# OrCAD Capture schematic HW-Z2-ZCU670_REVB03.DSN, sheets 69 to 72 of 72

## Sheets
69 069 Zynq Per-pin Decoupling 1: size Custom
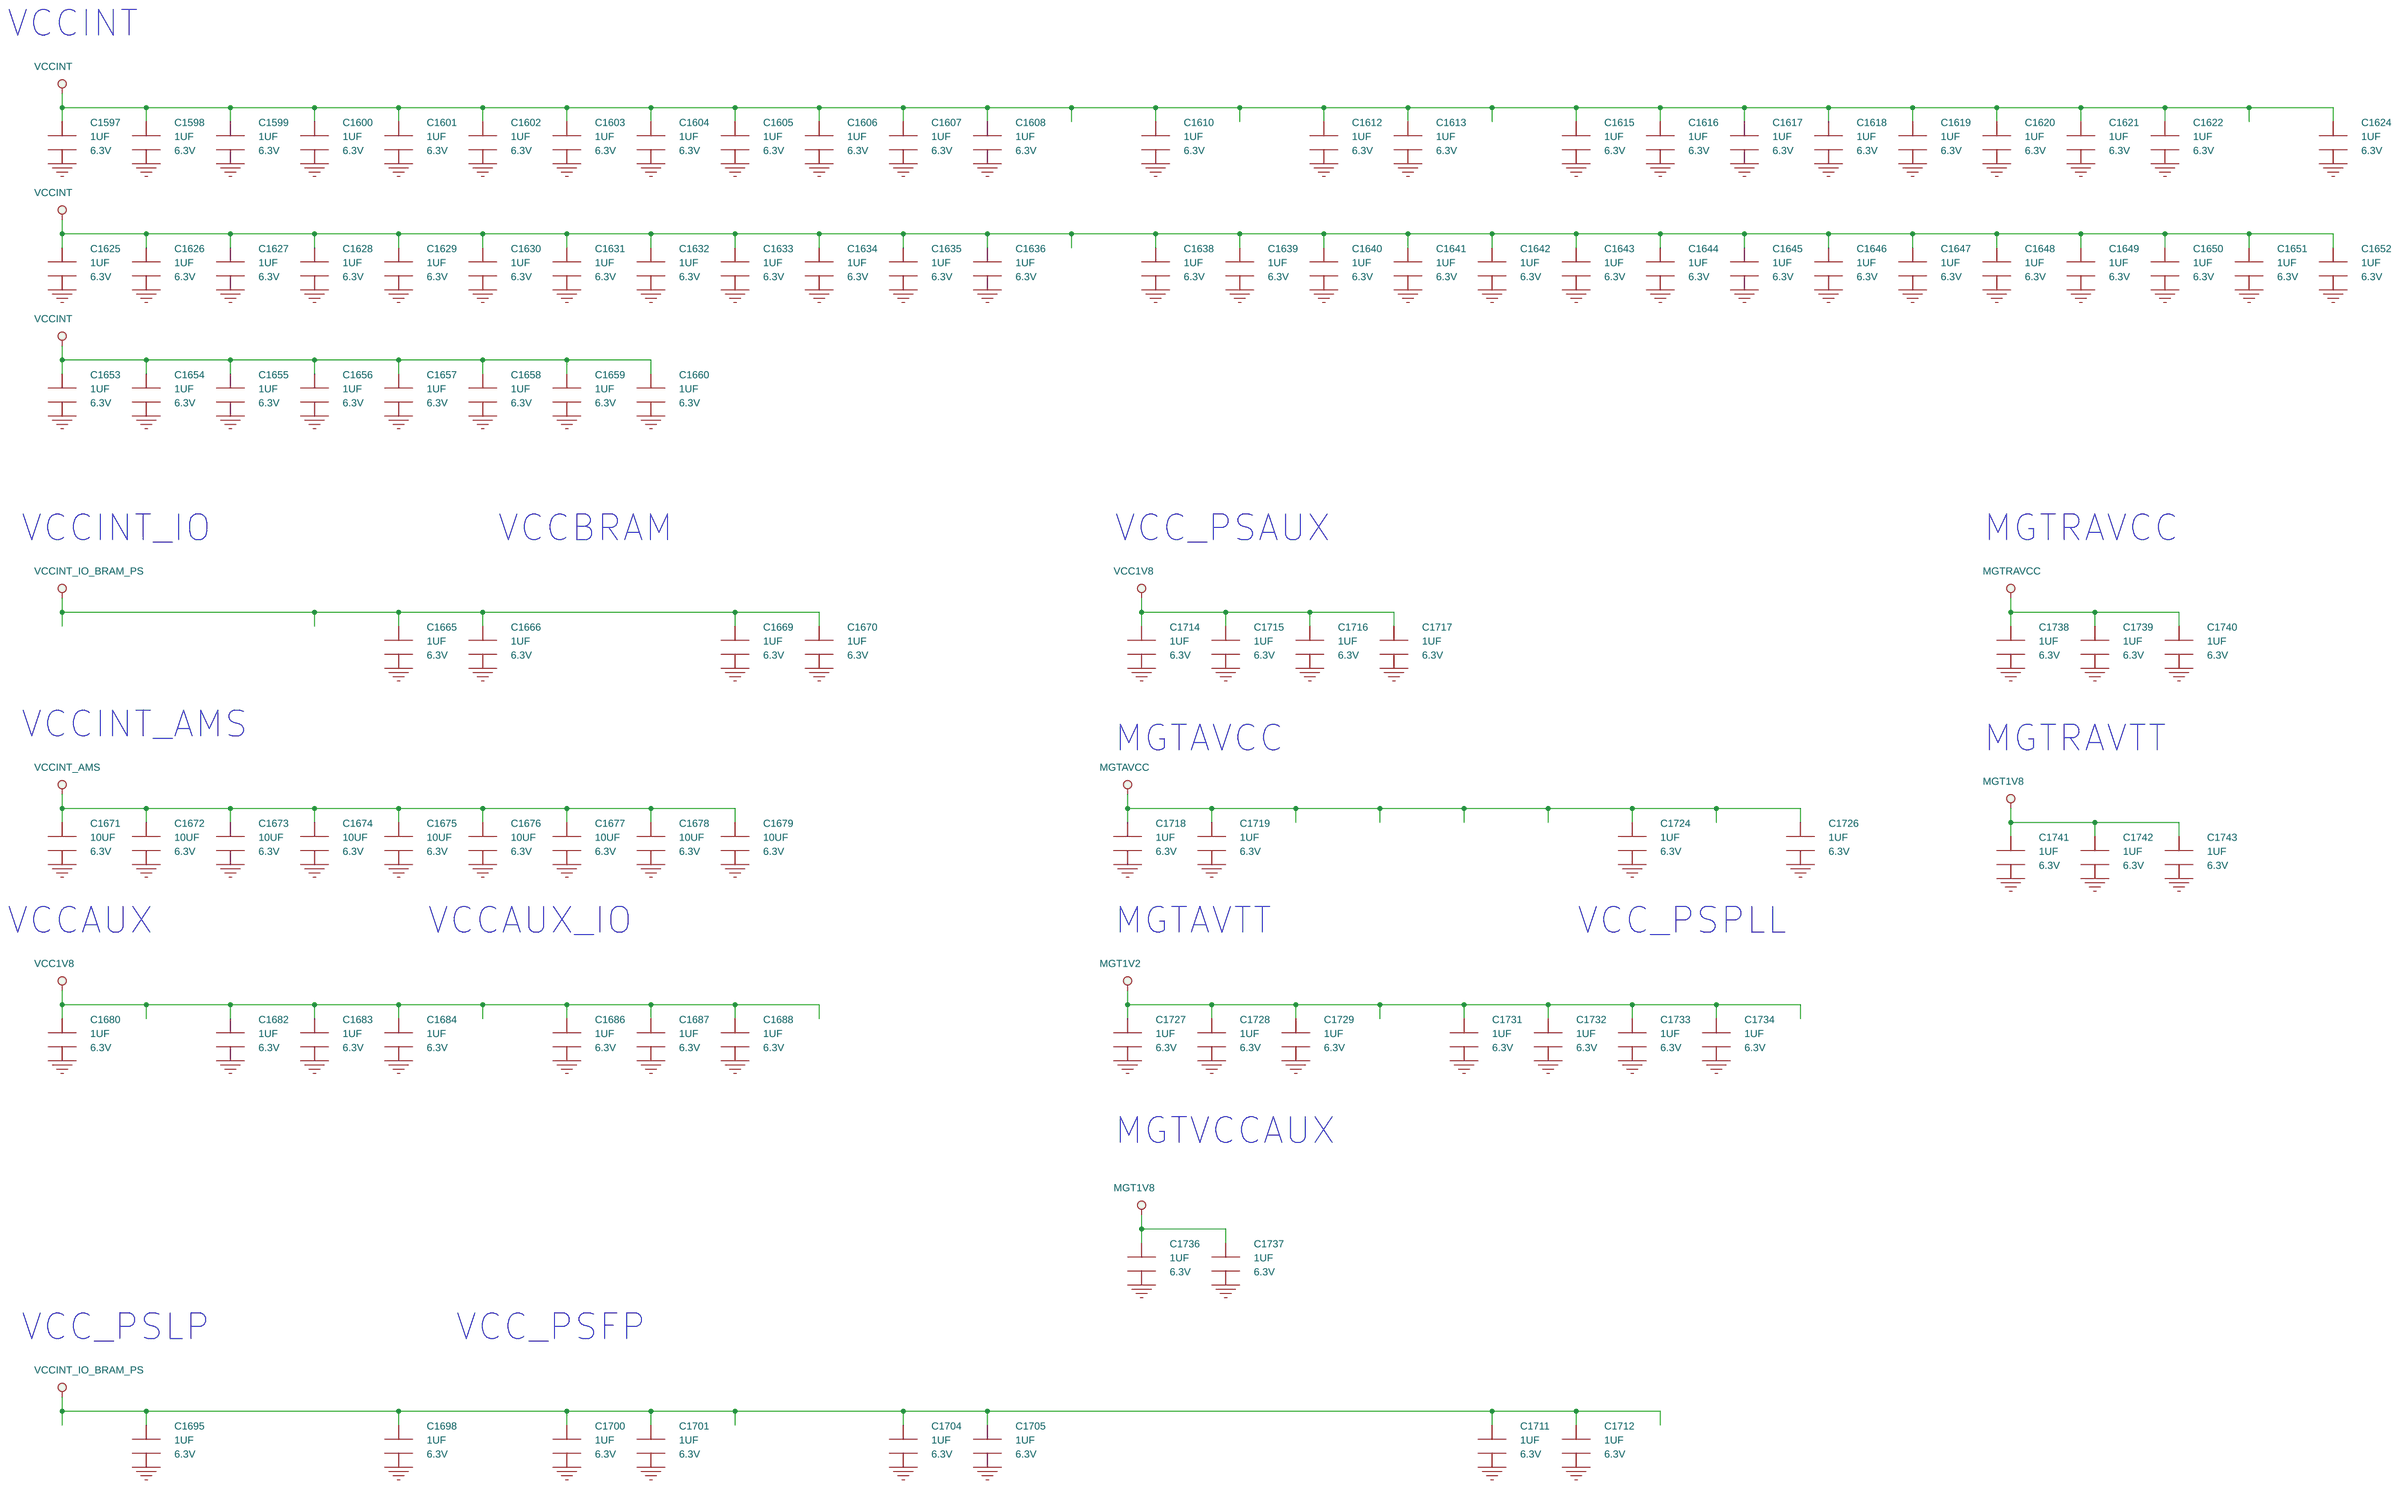
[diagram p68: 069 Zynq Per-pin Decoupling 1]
70 070 Zynq Per-pin Decoupling 2: size Custom
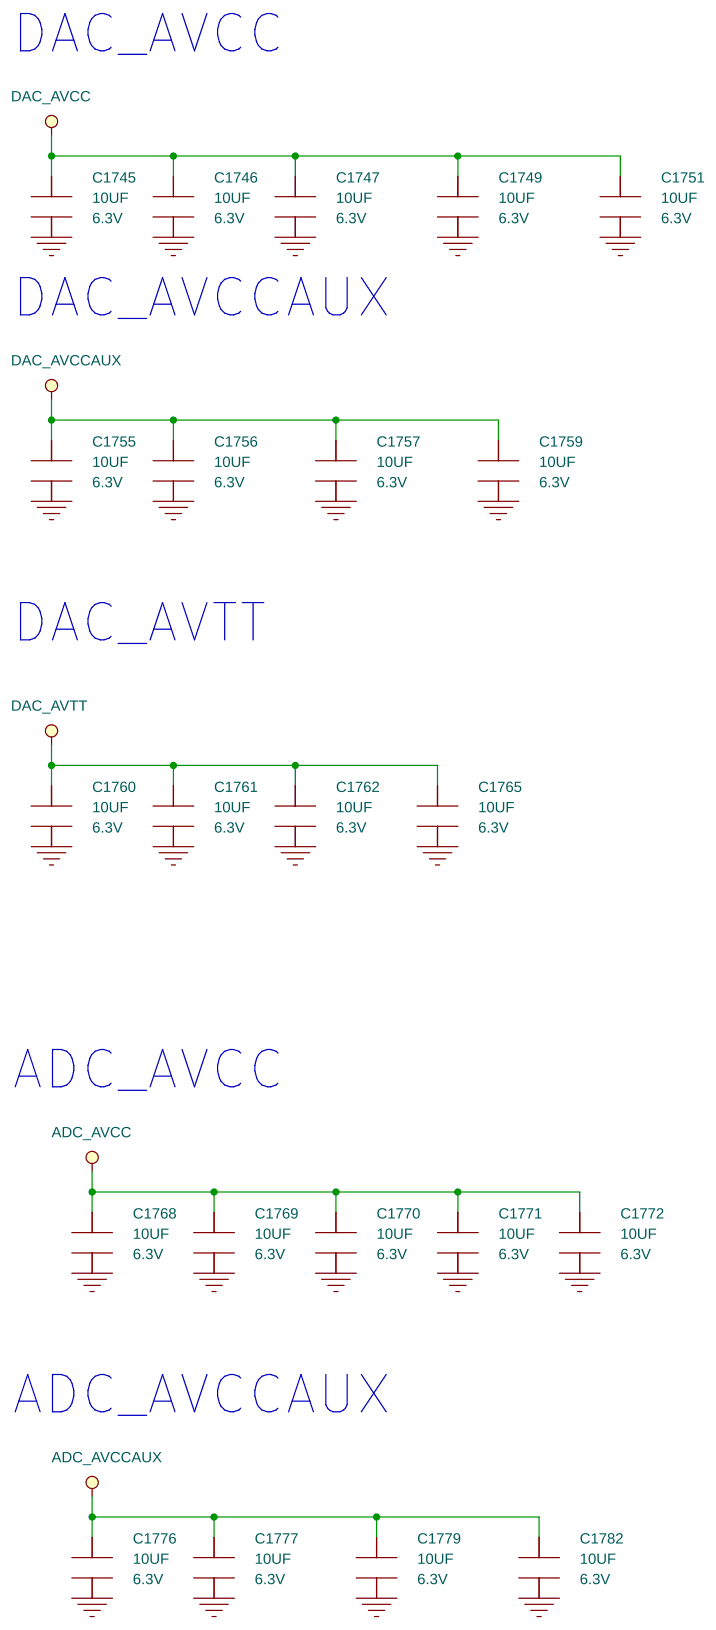
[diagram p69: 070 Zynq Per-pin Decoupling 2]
71 071 1588 eCPRI Power 1: size Custom
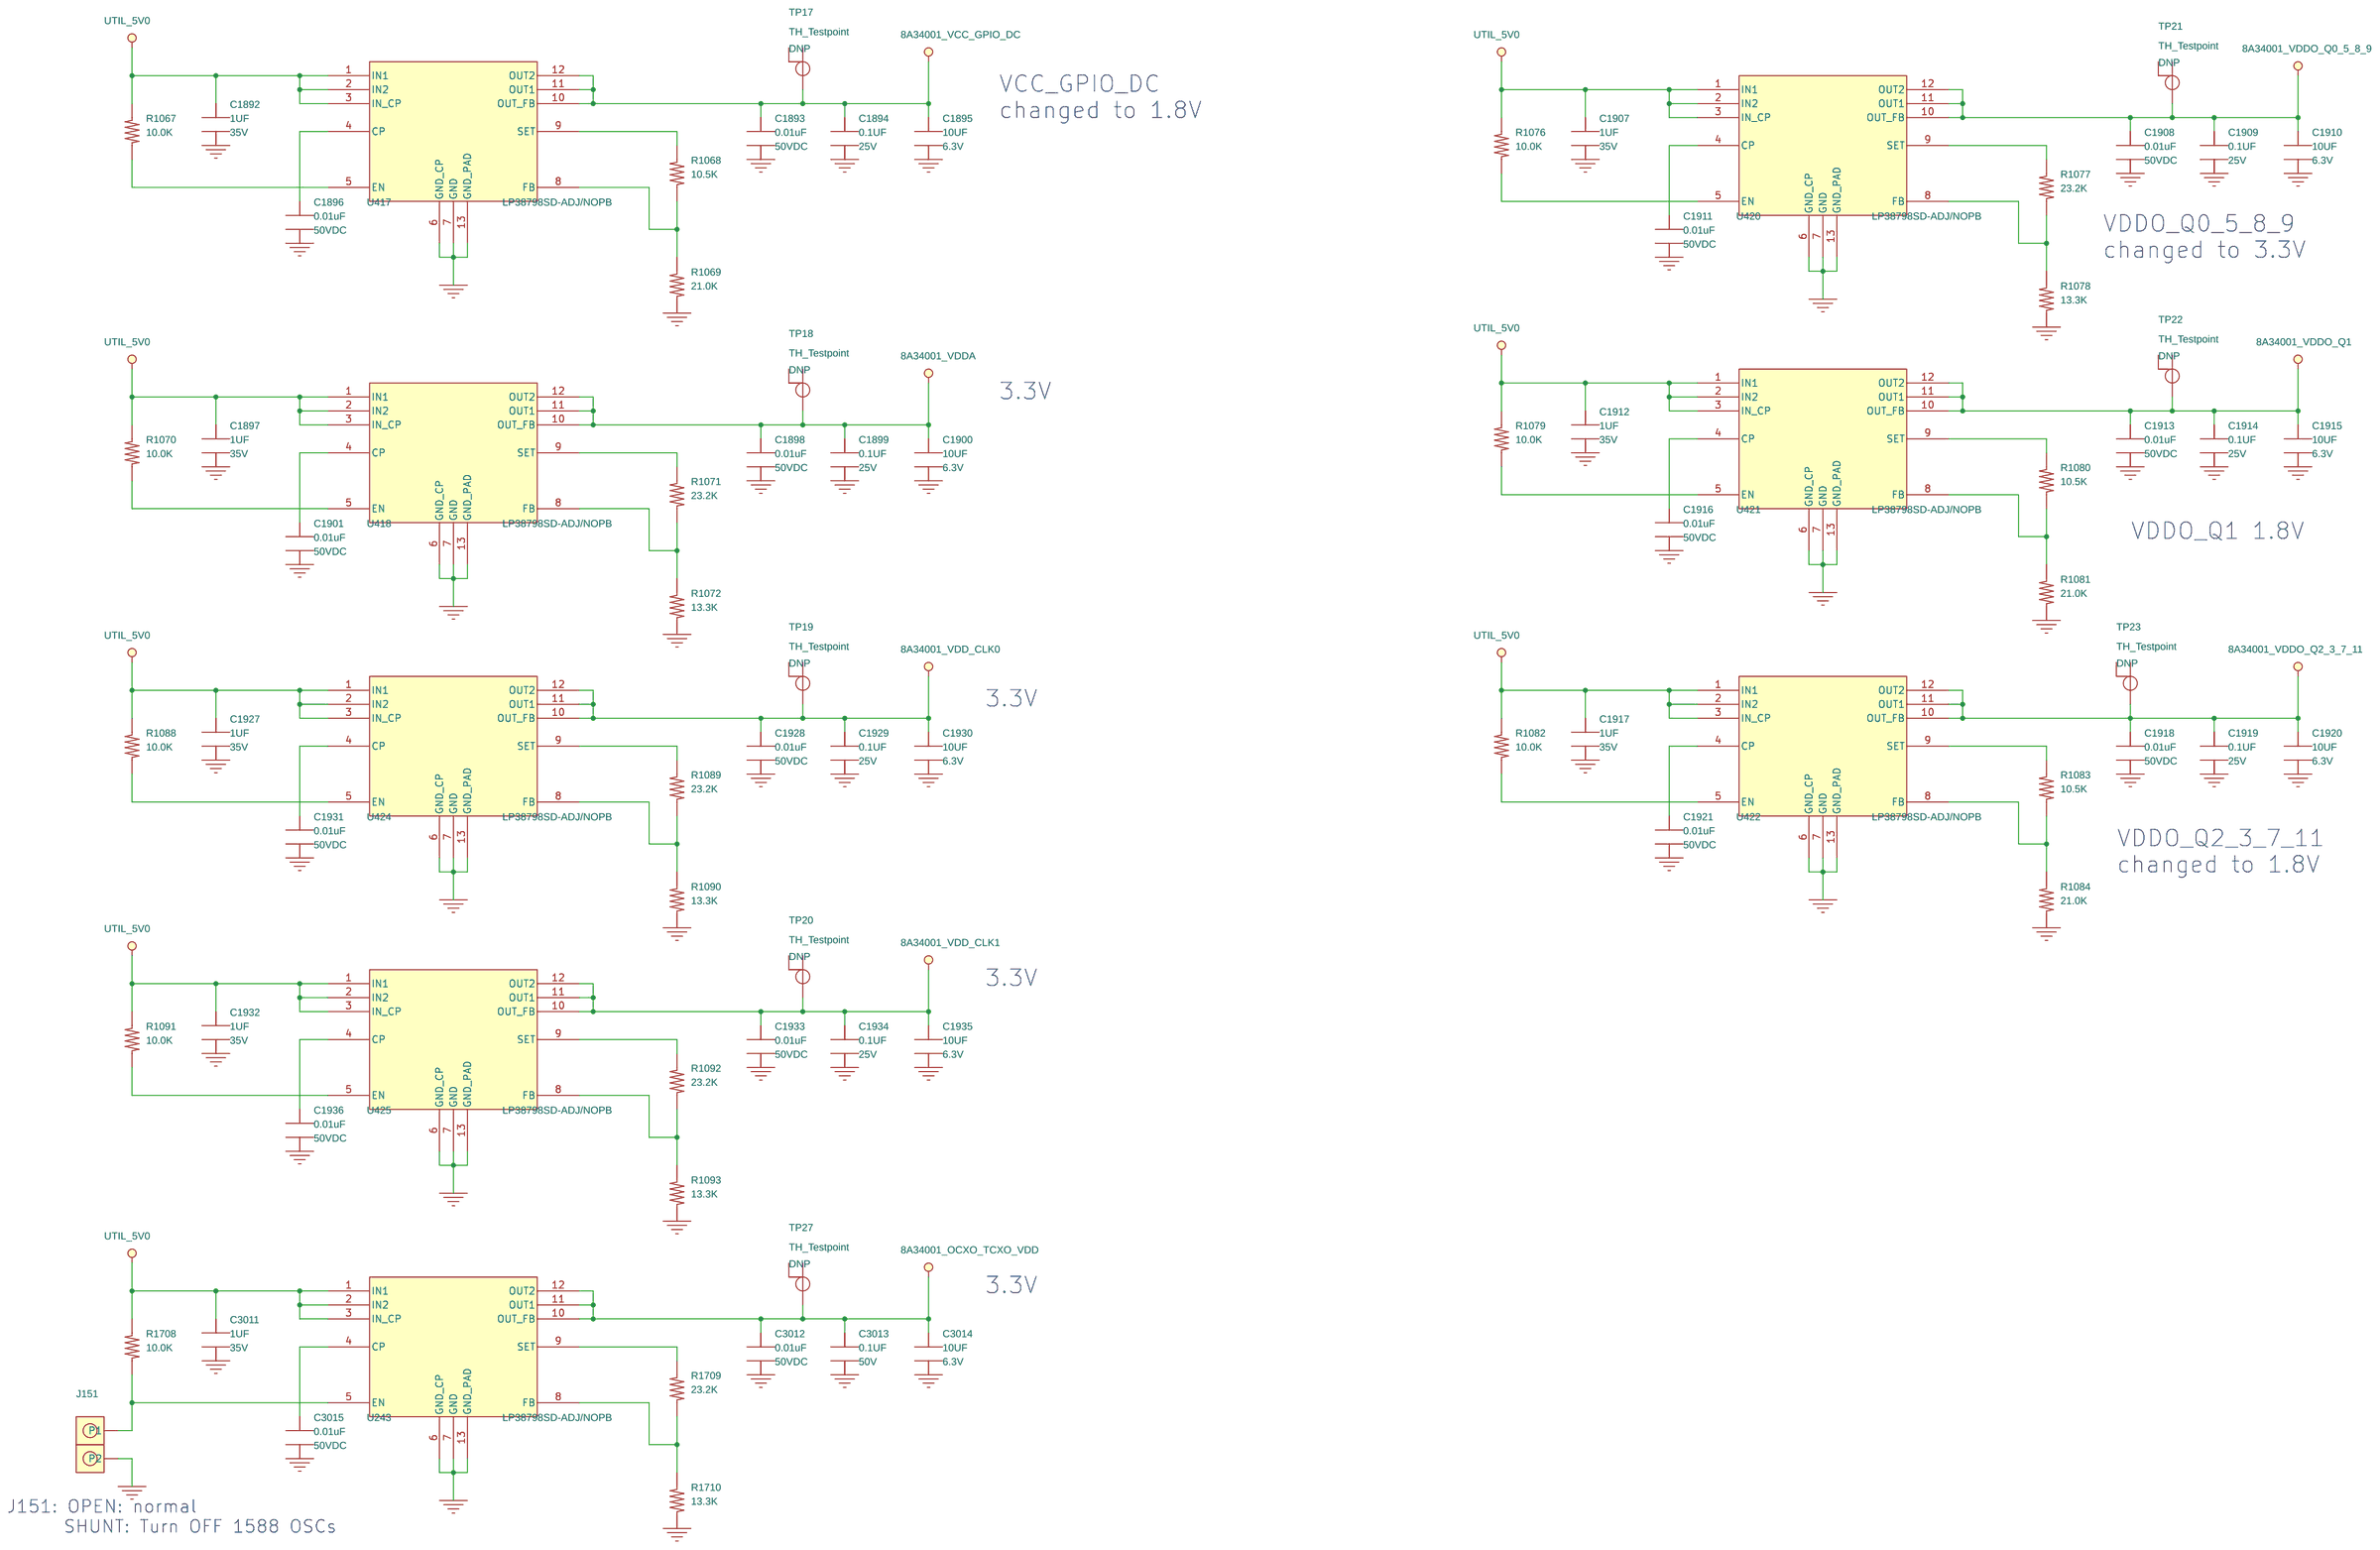
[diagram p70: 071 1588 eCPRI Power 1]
72 072 1588 eCPRI Power 2: size Custom
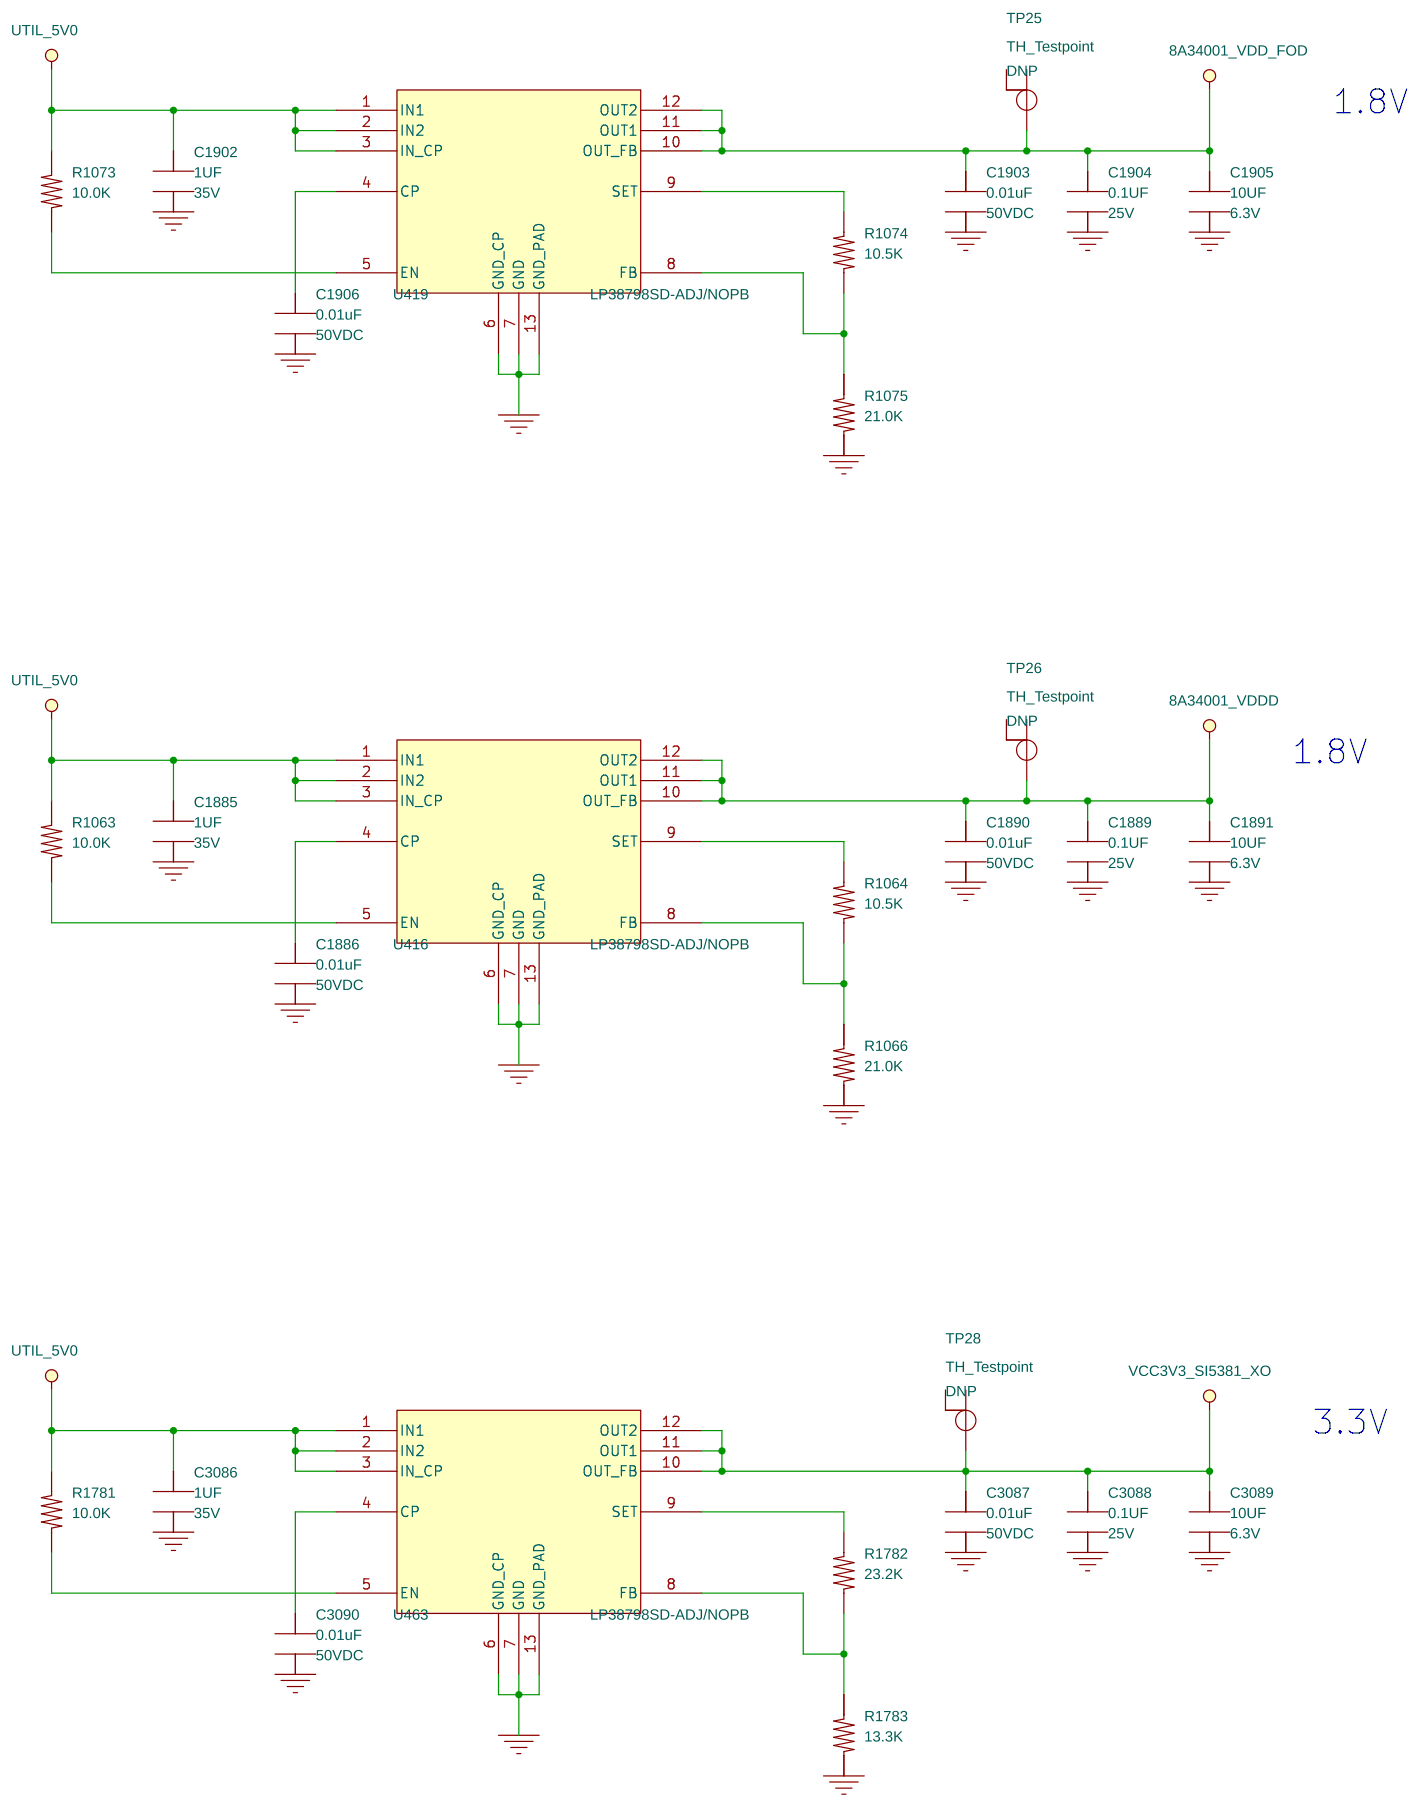
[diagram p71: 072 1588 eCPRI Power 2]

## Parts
sheet 069 Zynq Per-pin Decoupling 1
C1597  1UF  [CAPC60X30X40]
C1598  1UF  [CAPC60X30X40]
C1599  1UF  [CAPC60X30X40]
C1600  1UF  [CAPC60X30X40]
C1601  1UF  [CAPC60X30X40]
C1602  1UF  [CAPC60X30X40]
C1603  1UF  [CAPC60X30X40]
C1604  1UF  [CAPC60X30X40]
C1605  1UF  [CAPC60X30X40]
C1606  1UF  [CAPC60X30X40]
C1607  1UF  [CAPC60X30X40]
C1608  1UF  [CAPC60X30X40]
C1610  1UF  [CAPC60X30X40]
C1612  1UF  [CAPC60X30X40]
C1613  1UF  [CAPC60X30X40]
C1615  1UF  [CAPC60X30X40]
C1616  1UF  [CAPC60X30X40]
C1617  1UF  [CAPC60X30X40]
C1618  1UF  [CAPC60X30X40]
C1619  1UF  [CAPC60X30X40]
C1620  1UF  [CAPC60X30X40]
C1621  1UF  [CAPC60X30X40]
C1622  1UF  [CAPC60X30X40]
C1624  1UF  [CAPC60X30X40]
C1625  1UF  [CAPC60X30X40]
C1626  1UF  [CAPC60X30X40]
C1627  1UF  [CAPC60X30X40]
C1628  1UF  [CAPC60X30X40]
C1629  1UF  [CAPC60X30X40]
C1630  1UF  [CAPC60X30X40]
C1631  1UF  [CAPC60X30X40]
C1632  1UF  [CAPC60X30X40]
C1633  1UF  [CAPC60X30X40]
C1634  1UF  [CAPC60X30X40]
C1635  1UF  [CAPC60X30X40]
C1636  1UF  [CAPC60X30X40]
C1638  1UF  [CAPC60X30X40]
C1639  1UF  [CAPC60X30X40]
C1640  1UF  [CAPC60X30X40]
C1641  1UF  [CAPC60X30X40]
C1642  1UF  [CAPC60X30X40]
C1643  1UF  [CAPC60X30X40]
C1644  1UF  [CAPC60X30X40]
C1645  1UF  [CAPC60X30X40]
C1646  1UF  [CAPC60X30X40]
C1647  1UF  [CAPC60X30X40]
C1648  1UF  [CAPC60X30X40]
C1649  1UF  [CAPC60X30X40]
C1650  1UF  [CAPC60X30X40]
C1651  1UF  [CAPC60X30X40]
C1652  1UF  [CAPC60X30X40]
C1653  1UF  [CAPC60X30X40]
C1654  1UF  [CAPC60X30X40]
C1655  1UF  [CAPC60X30X40]
C1656  1UF  [CAPC60X30X40]
C1657  1UF  [CAPC60X30X40]
C1658  1UF  [CAPC60X30X40]
C1659  1UF  [CAPC60X30X40]
C1660  1UF  [CAPC60X30X40]
C1665  1UF  [CAPC60X30X40]
C1666  1UF  [CAPC60X30X40]
C1669  1UF  [CAPC60X30X40]
C1670  1UF  [CAPC60X30X40]
C1671  10UF  [CAPC100X50X70]
C1672  10UF  [CAPC100X50X70]
C1673  10UF  [CAPC100X50X70]
C1674  10UF  [CAPC100X50X70]
C1675  10UF  [CAPC100X50X70]
C1676  10UF  [CAPC100X50X70]
C1677  10UF  [CAPC100X50X70]
C1678  10UF  [CAPC100X50X70]
C1679  10UF  [CAPC100X50X70]
C1680  1UF  [CAPC60X30X40]
C1682  1UF  [CAPC60X30X40]
C1683  1UF  [CAPC60X30X40]
C1684  1UF  [CAPC60X30X40]
C1686  1UF  [CAPC60X30X40]
C1687  1UF  [CAPC60X30X40]
C1688  1UF  [CAPC60X30X40]
C1695  1UF  [CAPC60X30X40]
C1698  1UF  [CAPC60X30X40]
C1700  1UF  [CAPC60X30X40]
C1701  1UF  [CAPC60X30X40]
C1704  1UF  [CAPC60X30X40]
C1705  1UF  [CAPC60X30X40]
C1711  1UF  [CAPC60X30X40]
C1712  1UF  [CAPC60X30X40]
C1714  1UF  [CAPC60X30X40]
C1715  1UF  [CAPC60X30X40]
C1716  1UF  [CAPC60X30X40]
C1717  1UF  [CAPC60X30X40]
C1718  1UF  [CAPC60X30X40]
C1719  1UF  [CAPC60X30X40]
C1724  1UF  [CAPC60X30X40]
C1726  1UF  [CAPC60X30X40]
C1727  1UF  [CAPC60X30X40]
C1728  1UF  [CAPC60X30X40]
C1729  1UF  [CAPC60X30X40]
C1731  1UF  [CAPC60X30X40]
C1732  1UF  [CAPC60X30X40]
C1733  1UF  [CAPC60X30X40]
C1734  1UF  [CAPC60X30X40]
C1736  1UF  [CAPC60X30X40]
C1737  1UF  [CAPC60X30X40]
C1738  1UF  [CAPC60X30X40]
C1739  1UF  [CAPC60X30X40]
C1740  1UF  [CAPC60X30X40]
C1741  1UF  [CAPC60X30X40]
C1742  1UF  [CAPC60X30X40]
C1743  1UF  [CAPC60X30X40]
sheet 070 Zynq Per-pin Decoupling 2
C1745  10UF  [CAPC100X50X70]
C1746  10UF  [CAPC100X50X70]
C1747  10UF  [CAPC100X50X70]
C1749  10UF  [CAPC100X50X70]
C1751  10UF  [CAPC100X50X70]
C1755  10UF  [CAPC100X50X70]
C1756  10UF  [CAPC100X50X70]
C1757  10UF  [CAPC100X50X70]
C1759  10UF  [CAPC100X50X70]
C1760  10UF  [CAPC100X50X70]
C1761  10UF  [CAPC100X50X70]
C1762  10UF  [CAPC100X50X70]
C1765  10UF  [CAPC100X50X70]
C1768  10UF  [CAPC100X50X70]
C1769  10UF  [CAPC100X50X70]
C1770  10UF  [CAPC100X50X70]
C1771  10UF  [CAPC100X50X70]
C1772  10UF  [CAPC100X50X70]
C1776  10UF  [CAPC100X50X70]
C1777  10UF  [CAPC100X50X70]
C1779  10UF  [CAPC100X50X70]
C1782  10UF  [CAPC100X50X70]
sheet 071 1588 eCPRI Power 1
C1892  1UF  [CAPC100X50X60]
C1893  0.01uF  [CAPC100X50X55]
C1894  0.1UF  [CAPC100X50X55]
C1895  10UF  [CAPC100X50X70]
C1896  0.01uF  [CAPC100X50X55]
C1897  1UF  [CAPC100X50X60]
C1898  0.01uF  [CAPC100X50X55]
C1899  0.1UF  [CAPC100X50X55]
C1900  10UF  [CAPC100X50X70]
C1901  0.01uF  [CAPC100X50X55]
C1907  1UF  [CAPC100X50X60]
C1908  0.01uF  [CAPC100X50X55]
C1909  0.1UF  [CAPC100X50X55]
C1910  10UF  [CAPC100X50X70]
C1911  0.01uF  [CAPC100X50X55]
C1912  1UF  [CAPC100X50X60]
C1913  0.01uF  [CAPC100X50X55]
C1914  0.1UF  [CAPC100X50X55]
C1915  10UF  [CAPC100X50X70]
C1916  0.01uF  [CAPC100X50X55]
C1917  1UF  [CAPC100X50X60]
C1918  0.01uF  [CAPC100X50X55]
C1919  0.1UF  [CAPC100X50X55]
C1920  10UF  [CAPC100X50X70]
C1921  0.01uF  [CAPC100X50X55]
C1927  1UF  [CAPC100X50X60]
C1928  0.01uF  [CAPC100X50X55]
C1929  0.1UF  [CAPC100X50X55]
C1930  10UF  [CAPC100X50X70]
C1931  0.01uF  [CAPC100X50X55]
C1932  1UF  [CAPC100X50X60]
C1933  0.01uF  [CAPC100X50X55]
C1934  0.1UF  [CAPC100X50X55]
C1935  10UF  [CAPC100X50X70]
C1936  0.01uF  [CAPC100X50X55]
C3011  1UF  [CAPC100X50X60]
C3012  0.01uF  [CAPC100X50X55]
C3013  0.1UF  [CAPC100X50X55]
C3014  10UF  [CAPC100X50X70]
C3015  0.01uF  [CAPC100X50X55]
J151  HDR_1X2  [HDR_1X2]
R1067  10.0K  [RESC100X50X40]
R1068  10.5K  [RESC100X50X40]
R1069  21.0K  [RESC100X50X40]
R1070  10.0K  [RESC100X50X40]
R1071  23.2K  [RESC100X50X40]
R1072  13.3K  [RESC100X50X40]
R1076  10.0K  [RESC100X50X40]
R1077  23.2K  [RESC100X50X40]
R1078  13.3K  [RESC100X50X40]
R1079  10.0K  [RESC100X50X40]
R1080  10.5K  [RESC100X50X40]
R1081  21.0K  [RESC100X50X40]
R1082  10.0K  [RESC100X50X40]
R1083  10.5K  [RESC100X50X40]
R1084  21.0K  [RESC100X50X40]
R1088  10.0K  [RESC100X50X40]
R1089  23.2K  [RESC100X50X40]
R1090  13.3K  [RESC100X50X40]
R1091  10.0K  [RESC100X50X40]
R1092  23.2K  [RESC100X50X40]
R1093  13.3K  [RESC100X50X40]
R1708  10.0K  [RESC100X50X40]
R1709  23.2K  [RESC100X50X40]
R1710  13.3K  [RESC100X50X40]
TP17  TH_Testpoint  [TH_PAD]
TP18  TH_Testpoint  [TH_PAD]
TP19  TH_Testpoint  [TH_PAD]
TP20  TH_Testpoint  [TH_PAD]
TP21  TH_Testpoint  [TH_PAD]
TP22  TH_Testpoint  [TH_PAD]
TP23  TH_Testpoint  [TH_PAD]
TP27  TH_Testpoint  [TH_PAD]
U243  LP38798SD-ADJ/NOPB  [WSON05PX400X400X100_12_260X300]
U417  LP38798SD-ADJ/NOPB  [WSON05PX400X400X100_12_260X300]
U418  LP38798SD-ADJ/NOPB  [WSON05PX400X400X100_12_260X300]
U420  LP38798SD-ADJ/NOPB  [WSON05PX400X400X100_12_260X300]
U421  LP38798SD-ADJ/NOPB  [WSON05PX400X400X100_12_260X300]
U422  LP38798SD-ADJ/NOPB  [WSON05PX400X400X100_12_260X300]
U424  LP38798SD-ADJ/NOPB  [WSON05PX400X400X100_12_260X300]
U425  LP38798SD-ADJ/NOPB  [WSON05PX400X400X100_12_260X300]
sheet 072 1588 eCPRI Power 2
C1885  1UF  [CAPC100X50X60]
C1886  0.01uF  [CAPC100X50X55]
C1889  0.1UF  [CAPC100X50X55]
C1890  0.01uF  [CAPC100X50X55]
C1891  10UF  [CAPC100X50X70]
C1902  1UF  [CAPC100X50X60]
C1903  0.01uF  [CAPC100X50X55]
C1904  0.1UF  [CAPC100X50X55]
C1905  10UF  [CAPC100X50X70]
C1906  0.01uF  [CAPC100X50X55]
C3086  1UF  [CAPC100X50X60]
C3087  0.01uF  [CAPC100X50X55]
C3088  0.1UF  [CAPC100X50X55]
C3089  10UF  [CAPC100X50X70]
C3090  0.01uF  [CAPC100X50X55]
R1063  10.0K  [RESC100X50X40]
R1064  10.5K  [RESC100X50X40]
R1066  21.0K  [RESC100X50X40]
R1073  10.0K  [RESC100X50X40]
R1074  10.5K  [RESC100X50X40]
R1075  21.0K  [RESC100X50X40]
R1781  10.0K  [RESC100X50X40]
R1782  23.2K  [RESC100X50X40]
R1783  13.3K  [RESC100X50X40]
TP25  TH_Testpoint  [TH_PAD]
TP26  TH_Testpoint  [TH_PAD]
TP28  TH_Testpoint  [TH_PAD]
U416  LP38798SD-ADJ/NOPB  [WSON05PX400X400X100_12_260X300]
U419  LP38798SD-ADJ/NOPB  [WSON05PX400X400X100_12_260X300]
U463  LP38798SD-ADJ/NOPB  [WSON05PX400X400X100_12_260X300]

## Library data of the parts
C1597-C1608 C1610 C1612 C1613 C1615-C1622 C1624-C1636 C1638-C1660 C1665 C1666 C1669 C1670 C1680 C1682-C1684 C1686-C1688 C1695 C1698 C1700 C1701 C1704 C1705 C1711 C1712 C1714-C1719 C1724 C1726-C1729 C1731-C1734 C1736-C1743 = CAP_NP: Cap Cer 1uF 10% 6.3V X6S 0201; ALT_SYMBOLS: CAPC60X30X40RND,0201_BGA; Agile Part Number: CAP-00025-01; Barcode: 100337; CIP Link: http://xsjbrdwin1/CIP-E/Component/Index/All?pn=100337; Dielectric Type: X6S; Part Type: CERAMIC; Tolerance: 20%; Voltage: 6.3V
C1671-C1679 C1745-C1747 C1749 C1751 C1755-C1757 C1759-C1762 C1765 C1768-C1772 C1776 C1777 C1779 C1782 = CAP_NP: Cap Cer 10uF 20%  6.3V X6S 0402; ALT_SYMBOLS: CAPC100X50X55RND; Agile Part Number: CAP-00035-01; Barcode: 100268; CIP Link: http://xsjbrdwin1/CIP-E/Component/Index/All?pn=100268; Dielectric Type: X6S; Part Type: CERAMIC; Tolerance: 20%; Voltage: 6.3V
C1885 C1892 C1897 C1902 C1907 C1912 C1917 C1927 C1932 C3011 C3086 = CAP_NP: Cap Cer 1uF 10% 35V X5R 0402; ALT_SYMBOLS: CAPC100X50X60RND; Agile Part Number: CAP-00165-01; CIP Link: http://xsjbrdwin1/CIP-E/Component/Index/All?pn=100192; Dielectric Type: X5R; OWNER: 3709; PRICE: 0.04; Part Type: CERAMIC; PartType: CERAMIC; ROHS: Yes; Tolerance: 10%; Voltage: 35V; barcode: 100192
C1886 C1890 C1893 C1896 C1898 C1901 C1903 C1906 C1908 C1911 C1913 C1916 C1918 C1921 C1928 C1931 C1933 C1936 C3012 C3015 C3087 C3090 = CAP_NP: Cap Cer 10nF 10% 50V X7R 0402; ALT_SYMBOLS: CAPC100X50X55RND; Agile Part Number: CAP-00031-01; CIP Link: http://xsjbrdwin1/CIP-E/Component/Index/All?pn=100003; Dielectric Type: X7R; OWNER: 4001; PRICE: 0; Part Type: CERAMIC; PartType: CERAMIC; ROHS: Yes; Tolerance: 10%; Voltage: 50VDC; barcode: 100003
C1889 C1894 C1899 C1904 C1909 C1914 C1919 C1929 C1934 C3088 = CAP_NP: Cap Cer 100nF 10% 25V X5R 0402; ALT_SYMBOLS: CAPC100X50X55RND; Agile Part Number: CAP-00068-01; CIP Link: http://xsjbrdwin1/CIP-E/Component/Index/All?pn=100040; Dielectric Type: X5R; OWNER: 4001; PRICE: 0.01; Part Type: CERAMIC; PartType: CERAMIC; ROHS: Yes; Tolerance: 10%; Voltage: 25V; barcode: 100040
C1891 C1895 C1900 C1905 C1910 C1915 C1920 C1930 C1935 C3014 C3089 = CAP_NP: Cap Cer 10uF 20%  6.3V X6S 0402; ALT_SYMBOLS: CAPC100X50X55RND; Agile Part Number: CAP-00035-01; CIP Link: http://xsjbrdwin1/CIP-E/Component/Index/All?pn=100268; Dielectric Type: X6S; OWNER: 3670; PRICE: 0.04; Part Type: CERAMIC; PartType: CERAMIC; ROHS: Yes; Tolerance: 20%; Voltage: 6.3V; barcode: 100268
C3013 = CAP_NP: Cap Cer 100nF 10% 50V X7R 0402; ALT_SYMBOLS: CAPC100X50X55RND; Agile Part Number: CAP-00022-01; CIP Link: http://xsjbrdwin1/CIP-E/Component/Index/All?pn=100170; Dielectric Type: X7R; OWNER: 4001; PRICE: 0.01; Part Type: CERAMIC; PartType: CERAMIC; ROHS: Yes; Tolerance: 10%; Voltage: 50V; barcode: 100170
J151 = HDR_1X2: Conn Hdr Male Vert 2 Pos 1x2 2.54mm P Black TH; Agile Part Number: CON-00037-01; Barcode: 390102; CIP Link: http://xsjbrdwin1/CIP-E/Component/Index/All?pn=390102; OWNER: 4001; PRICE: 0.03; Part Type: HEADER; PartType: HEADER; Pins: 2PINS; Pitch: 0.100; ROHS: Yes
R1063 R1067 R1070 R1073 R1076 R1079 R1082 R1088 R1091 R1708 R1781 = RES: Res 10K 1% 1/16W 100PPM 50V 0402; ALT_SYMBOLS: RESC100X50X40RND; Agile Part Number: RES-00030-01; Barcode: 200025; CIP Link: http://xsjbrdwin1/CIP-E/Component/Index/All?pn=200025; Part Type: SMT - 1%; Rated Power: 1/16W; Tolerance: 1%
R1064 R1068 R1074 R1080 R1083 = RES: Res 10K5 1% 1/16W 100PPM 50V 0402; Agile Part Number: RES-00211-01; Barcode: 200224; CIP Link: http://xsjbrdwin1/CIP-E/Component/Index/All?pn=200224; Part Type: SMT - 1%; Rated Power: 1/16W; Tolerance: 1%
R1066 R1069 R1075 R1081 R1084 = RES: Res 21K 1% 1/16W 100PPM 50V 0402; ALT_SYMBOLS: 0402; Agile Part Number: RES-00005-01; Barcode: 200569; CIP Link: http://xsjbrdwin1/CIP-E/Component/Index/All?pn=200569; Part Type: SMT - 1%; Rated Power: 1/16W; Tolerance: 1%
R1071 R1077 R1089 R1092 R1709 R1782 = RES: Res 23K2 1% 1/16W 100PPM 50V 0402; ALT_SYMBOLS: (0402,C402-25,RESC100X50X40L25NRND); Agile Part Number: RES-00203-01; Barcode: 200215; CIP Link: http://xsjbrdwin1/CIP-E/Component/Index/All?pn=200215; Part Type: SMT - 1%; Rated Power: 1/16W; Tolerance: 1%
R1072 R1078 R1090 R1093 R1710 R1783 = RES: Res 13K3 1% 1/16W 100PPM 50V 0402; Agile Part Number: RES-00389-01; Barcode: 200431; CIP Link: http://xsjbrdwin1/CIP-E/Component/Index/All?pn=200431; Part Type: SMT - 1%; Rated Power: 1/16W; Tolerance: 1%
TP17-TP23 TP25-TP28 = TP: TEST POINT 24mil hole 12mil via; ASSEMBLY_OPTIONS: DNP; Barcode: 96000017; CIP Link: http://xsjbrdwin1/CIP-E/Component/Index/All?pn=96000017; Part Type: Unassigned Part Type
U243 U416-U422 U424 U425 U463 = LP38798: IC LDO 20V 899mA Adj WSON-12; Agile Part Number: ICS-00517-01; Barcode: 50000046; CIP Link: http://xsjbrdwin1/CIP-E/Component/Index/All?pn=50000046; Part Type: Unassigned Part Type

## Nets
GND: C1597.2 C1598.2 C1599.2 C1600.2 C1601.2 C1602.2 C1603.2 C1604.2 C1605.2 C1606.2 C1607.2 C1608.2 C1610.2 C1612.2 C1613.2 C1615.2 C1616.2 C1617.2 C1618.2 C1619.2 C1620.2 C1621.2 C1622.2 C1624.2 C1625.2 C1626.2 C1627.2 C1628.2 C1629.2 C1630.2 C1631.2 C1632.2 C1633.2 C1634.2 C1635.2 C1636.2 C1638.2 C1639.2 C1640.2 C1641.2 C1642.2 C1643.2 C1644.2 C1645.2 C1646.2 C1647.2 C1648.2 C1649.2 C1650.2 C1651.2 C1652.2 C1653.2 C1654.2 C1655.2 C1656.2 C1657.2 C1658.2 C1659.2 C1660.2 C1665.2 C1666.2 C1669.2 C1670.2 C1671.2 C1672.2 C1673.2 C1674.2 C1675.2 C1676.2 C1677.2 C1678.2 C1679.2 C1680.2 C1682.2 C1683.2 C1684.2 C1686.2 C1687.2 C1688.2 C1695.2 C1698.2 C1700.2 C1701.2 C1704.2 C1705.2 C1711.2 C1712.2 C1714.2 C1715.2 C1716.2 C1717.2 C1718.2 C1719.2 C1724.2 C1726.2 C1727.2 C1728.2 C1729.2 C1731.2 C1732.2 C1733.2 C1734.2 C1736.2 C1737.2 C1738.2 C1739.2 C1740.2 C1741.2 C1742.2 C1743.2 C1745.2 C1746.2 C1747.2 C1749.2 C1751.2 C1755.2 C1756.2 C1757.2 C1759.2 C1760.2 C1761.2 C1762.2 C1765.2 C1768.2 C1769.2 C1770.2 C1771.2 C1772.2 C1776.2 C1777.2 C1779.2 C1782.2 C1885.2 C1886.2 C1889.2 C1890.2 C1891.2 C1892.2 C1893.2 C1894.2 C1895.2 C1896.2 C1897.2 C1898.2 C1899.2 C1900.2 C1901.2 C1902.2 C1903.2 C1904.2 C1905.2 C1906.2 C1907.2 C1908.2 C1909.2 C1910.2 C1911.2 C1912.2 C1913.2 C1914.2 C1915.2 C1916.2 C1917.2 C1918.2 C1919.2 C1920.2 C1921.2 C1927.2 C1928.2 C1929.2 C1930.2 C1931.2 C1932.2 C1933.2 C1934.2 C1935.2 C1936.2 C3011.2 C3012.2 C3013.2 C3014.2 C3015.2 C3086.2 C3087.2 C3088.2 C3089.2 C3090.2 J151.2(P2) R1066.2 R1069.2 R1072.2 R1075.2 R1078.2 R1081.2 R1084.2 R1090.2 R1093.2 R1710.2 R1783.2 U243.6(GND_CP) U243.7(GND) U243.13(GND_PAD) U416.6(GND_CP) U416.7(GND) U416.13(GND_PAD) U417.6(GND_CP) U417.7(GND) U417.13(GND_PAD) U418.6(GND_CP) U418.7(GND) U418.13(GND_PAD) U419.6(GND_CP) U419.7(GND) U419.13(GND_PAD) U420.6(GND_CP) U420.7(GND) U420.13(GND_PAD) U421.6(GND_CP) U421.7(GND) U421.13(GND_PAD) U422.6(GND_CP) U422.7(GND) U422.13(GND_PAD) U424.6(GND_CP) U424.7(GND) U424.13(GND_PAD) U425.6(GND_CP) U425.7(GND) U425.13(GND_PAD) U463.6(GND_CP) U463.7(GND) U463.13(GND_PAD) ; also on sheet 3 4 5 7 8 9 10 11 12 13 14 16 17 18 19 20 21 22 23 24 25 26 27 28 32 33 34 35 36 37 38 39 40 41 42 43 44 45 46 47 48 49 50 51 52 53 54 55 56 57 58 59 60 61 62 63 64 65 66 67 68
VCC1V8: C1680.1 C1682.1 C1683.1 C1684.1 C1686.1 C1687.1 C1688.1 C1714.1 C1715.1 C1716.1 C1717.1 ; also on sheet 3 5 9 10 15 16 17 52
VCC3V3_Si5381_XO: C3087.1 C3088.1 C3089.1 TP28.1(TP) U463.10(OUT_FB) U463.11(OUT1) U463.12(OUT2) ; also on sheet 36
VCCINT: C1597.1 C1598.1 C1599.1 C1600.1 C1601.1 C1602.1 C1603.1 C1604.1 C1605.1 C1606.1 C1607.1 C1608.1 C1610.1 C1612.1 C1613.1 C1615.1 C1616.1 C1617.1 C1618.1 C1619.1 C1620.1 C1621.1 C1622.1 C1624.1 C1625.1 C1626.1 C1627.1 C1628.1 C1629.1 C1630.1 C1631.1 C1632.1 C1633.1 C1634.1 C1635.1 C1636.1 C1638.1 C1639.1 C1640.1 C1641.1 C1642.1 C1643.1 C1644.1 C1645.1 C1646.1 C1647.1 C1648.1 C1649.1 C1650.1 C1651.1 C1652.1 C1653.1 C1654.1 C1655.1 C1656.1 C1657.1 C1658.1 C1659.1 C1660.1 ; also on sheet 3 15 17 44 45
VCCINT_AMS: C1671.1 C1672.1 C1673.1 C1674.1 C1675.1 C1676.1 C1677.1 C1678.1 C1679.1 ; also on sheet 15 44 45
VCCINT_IO_BRAM_PS: C1665.1 C1666.1 C1669.1 C1670.1 C1695.1 C1698.1 C1700.1 C1701.1 C1704.1 C1705.1 C1711.1 C1712.1 ; also on sheet 15 16 17 50
8A34001_OCXO_TCXO_VDD: C3012.1 C3013.1 C3014.1 TP27.1(TP) U243.10(OUT_FB) U243.11(OUT1) U243.12(OUT2) ; also on sheet 34
8A34001_VCC_GPIO_DC: C1893.1 C1894.1 C1895.1 TP17.1(TP) U417.10(OUT_FB) U417.11(OUT1) U417.12(OUT2) ; also on sheet 34 35
8A34001_VDD_CLK0: C1928.1 C1929.1 C1930.1 TP19.1(TP) U424.10(OUT_FB) U424.11(OUT1) U424.12(OUT2) ; also on sheet 35 38
8A34001_VDD_CLK1: C1933.1 C1934.1 C1935.1 TP20.1(TP) U425.10(OUT_FB) U425.11(OUT1) U425.12(OUT2) ; also on sheet 35 38
8A34001_VDD_FOD: C1903.1 C1904.1 C1905.1 TP25.1(TP) U419.10(OUT_FB) U419.11(OUT1) U419.12(OUT2) ; also on sheet 35
8A34001_VDDA: C1898.1 C1899.1 C1900.1 TP18.1(TP) U418.10(OUT_FB) U418.11(OUT1) U418.12(OUT2) ; also on sheet 35
8A34001_VDDD: C1889.1 C1890.1 C1891.1 TP26.1(TP) U416.10(OUT_FB) U416.11(OUT1) U416.12(OUT2) ; also on sheet 35
8A34001_VDDO_Q0_5_8_9: C1908.1 C1909.1 C1910.1 TP21.1(TP) U420.10(OUT_FB) U420.11(OUT1) U420.12(OUT2) ; also on sheet 35
8A34001_VDDO_Q1: C1913.1 C1914.1 C1915.1 TP22.1(TP) U421.10(OUT_FB) U421.11(OUT1) U421.12(OUT2) ; also on sheet 35
8A34001_VDDO_Q2_3_7_11: C1918.1 C1919.1 C1920.1 TP23.1(TP) U422.10(OUT_FB) U422.11(OUT1) U422.12(OUT2) ; also on sheet 35
ADC_AVCC: C1768.1 C1769.1 C1770.1 C1771.1 C1772.1 ; also on sheet 13 53
ADC_AVCCAUX: C1776.1 C1777.1 C1779.1 C1782.1 ; also on sheet 13 54
DAC_AVCC: C1745.1 C1746.1 C1747.1 C1749.1 C1751.1 ; also on sheet 14 53
DAC_AVCCAUX: C1755.1 C1756.1 C1757.1 C1759.1 ; also on sheet 14 55
DAC_AVTT: C1760.1 C1761.1 C1762.1 C1765.1 ; also on sheet 14 55
MGT1V2: C1727.1 C1728.1 C1729.1 C1731.1 C1732.1 C1733.1 C1734.1 ; also on sheet 6 15 16 17 18 49
MGT1V8: C1736.1 C1737.1 C1741.1 C1742.1 C1743.1 ; also on sheet 15 16 18 47
MGTAVCC: C1718.1 C1719.1 C1724.1 C1726.1 ; also on sheet 15 18 51
MGTRAVCC: C1738.1 C1739.1 C1740.1 ; also on sheet 16 18 49
UTIL_5V0: C1885.1 C1892.1 C1897.1 C1902.1 C1907.1 C1912.1 C1917.1 C1927.1 C1932.1 C3011.1 C3086.1 R1063.1 R1067.1 R1070.1 R1073.1 R1076.1 R1079.1 R1082.1 R1088.1 R1091.1 R1708.1 R1781.1 U243.1(IN1) U243.2(IN2) U243.3(IN_CP) U416.1(IN1) U416.2(IN2) U416.3(IN_CP) U417.1(IN1) U417.2(IN2) U417.3(IN_CP) U418.1(IN1) U418.2(IN2) U418.3(IN_CP) U419.1(IN1) U419.2(IN2) U419.3(IN_CP) U420.1(IN1) U420.2(IN2) U420.3(IN_CP) U421.1(IN1) U421.2(IN2) U421.3(IN_CP) U422.1(IN1) U422.2(IN2) U422.3(IN_CP) U424.1(IN1) U424.2(IN2) U424.3(IN_CP) U425.1(IN1) U425.2(IN2) U425.3(IN_CP) U463.1(IN1) U463.2(IN2) U463.3(IN_CP) ; also on sheet 20 44 45 48 53 54 55 58 60 62 64
N26881032: C1896.1 U417.4(CP)
N26881036: R1068.1 U417.9(SET)
N26881084: R1067.2 U417.5(EN)
N26881106: R1068.2 R1069.1 U417.8(FB)
N26881618: C1901.1 U418.4(CP)
N26881622: R1071.1 U418.9(SET)
N26881670: R1070.2 U418.5(EN)
N26881692: R1071.2 R1072.1 U418.8(FB)
N26884082: C1911.1 U420.4(CP)
N26884086: R1077.1 U420.9(SET)
N26884134: R1076.2 U420.5(EN)
N26884156: R1077.2 R1078.1 U420.8(FB)
N26885607: C1916.1 U421.4(CP)
N26885611: R1080.1 U421.9(SET)
N26885659: R1079.2 U421.5(EN)
N26885681: R1080.2 R1081.1 U421.8(FB)
N26885844: C1921.1 U422.4(CP)
N26885848: R1083.1 U422.9(SET)
N26885896: R1082.2 U422.5(EN)
N26885918: R1083.2 R1084.1 U422.8(FB)
N26886318: C1931.1 U424.4(CP)
N26886322: R1089.1 U424.9(SET)
N26886370: R1088.2 U424.5(EN)
N26886392: R1089.2 R1090.1 U424.8(FB)
N26892159: C1906.1 U419.4(CP)
N26892163: R1074.1 U419.9(SET)
N26892211: R1073.2 U419.5(EN)
N26892233: R1074.2 R1075.1 U419.8(FB)
N26893692: C1936.1 U425.4(CP)
N26893696: R1092.1 U425.9(SET)
N26893744: R1091.2 U425.5(EN)
N26893766: R1092.2 R1093.1 U425.8(FB)
N26894568: C1886.1 U416.4(CP)
N26894572: R1064.1 U416.9(SET)
N26894620: R1063.2 U416.5(EN)
N26894642: R1064.2 R1066.1 U416.8(FB)
N29745862: C3015.1 U243.4(CP)
N29745866: R1709.1 U243.9(SET)
N29745914: J151.1(P1) R1708.2 U243.5(EN)
N29745936: R1709.2 R1710.1 U243.8(FB)
N32589602: C3090.1 U463.4(CP)
N32589606: R1782.1 U463.9(SET)
N32589654: R1781.2 U463.5(EN)
N32589676: R1782.2 R1783.1 U463.8(FB)

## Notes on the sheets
sheet 69
- VCCINT
- VCCINT_IO
- VCCBRAM
- VCC_PSAUX
- MGTRAVCC
- VCCINT_AMS
- MGTAVCC
- MGTRAVTT
- VCCAUX
- VCCAUX_IO
- MGTAVTT
- VCC_PSPLL
- MGTVCCAUX
- VCC_PSLP
- VCC_PSFP
sheet 70
- DAC_AVCC
- DAC_AVCCAUX
- DAC_AVTT
- ADC_AVCC
- ADC_AVCCAUX
sheet 71
- VCC_GPIO_DC
  changed to 1.8V
- VDDO_Q0_5_8_9
  changed to 3.3V
- 3.3V
- VDDO_Q1 1.8V
- 3.3V
- VDDO_Q2_3_7_11
  changed to 1.8V
- 3.3V
- 3.3V
- J151: OPEN: normal
        SHUNT: Turn OFF 1588 OSCs
sheet 72
- 1.8V
- 1.8V
- 3.3V
